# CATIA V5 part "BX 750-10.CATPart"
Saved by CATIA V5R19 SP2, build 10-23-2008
Part number: BX 750-10
Bounding box of the stored display mesh (mm): x -47.487 to 47.487, y -47.487 to 47.487, z 0 to 90
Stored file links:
  C:\Users\Bora\Desktop\3D Katı model\BX serisi\BX 750\BX 750-10.CATPart
  C:\Program Files\Dassault Systemes\B19\intel_a\reffiles\standard\MetricThickPitch.txt
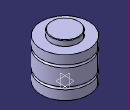
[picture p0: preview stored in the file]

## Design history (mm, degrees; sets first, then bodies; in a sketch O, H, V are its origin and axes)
Body1 (main body)
  Sketch1 on yz-plane, origin (0, 0, 0), H (0, 1, 0), V (0, 0, 1)
    point P1 (47.5, 56.5)
    point P2 (47.5, 61.5)
    arc A1 centre (47.5, 59) radius 2.5 from (47.5, 61.5) to (47.5, 56.5) ccw
    point P3 (47.5, 18.5)
    point P4 (47.5, 23.5)
    arc A2 centre (47.5, 21) radius 2.5 from (47.5, 23.5) to (47.5, 18.5) ccw
    point P5 (47.5, 61.5)
    line L1 (47.5, 79) -> (47.5, 61.5)
    point P8 (27.5, 89)
    line L2 (27.5, 89) -> (27.5, 79)
    point P10 (27.5, 89)
    arc A3 centre (26.5, 89) radius 1 from (27.5, 89) to (26.5, 90) ccw
    point P11 (47.5, 23.5)
    point P12 (47.5, 56.5)
    line L3 (47.5, 56.5) -> (47.5, 23.5)
    point P14 (47.5, 18.5)
    line L4 (47.5, 18.5) -> (47.5, 0)
    line L5 (26.5, 90) -> (0, 90)
    line L6 (27.5, 79) -> (47.5, 79)
    line L7 (47.5, 0) -> (0, 0)
    tangency: L5 A3
    horizontal: L6 H, L7 H
    coincidence: P1 P12, P2 P5, P3 P14, P4 P11, P8 P10
  Shaft1: profile Sketch1, axis Sketch1.V, angle 360
  Sketch2 on face of Shaft1 from Sketch1.L7, origin (0, 0, 0), H (1, 0, 0), V (0, -1, 0)
    point P1 (25, 0)
    distance P1 V = 25
  Hole1: placed by Sketch2, at (25, 0, 0) direction (0, 0, 1), diameter 6.647, depth 10, threaded "M8", thread diameter 8, thread depth 10, pitch 1.25
  CircPattern1: of Hole1, instances 4, angular step 90, axis from xy-plane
